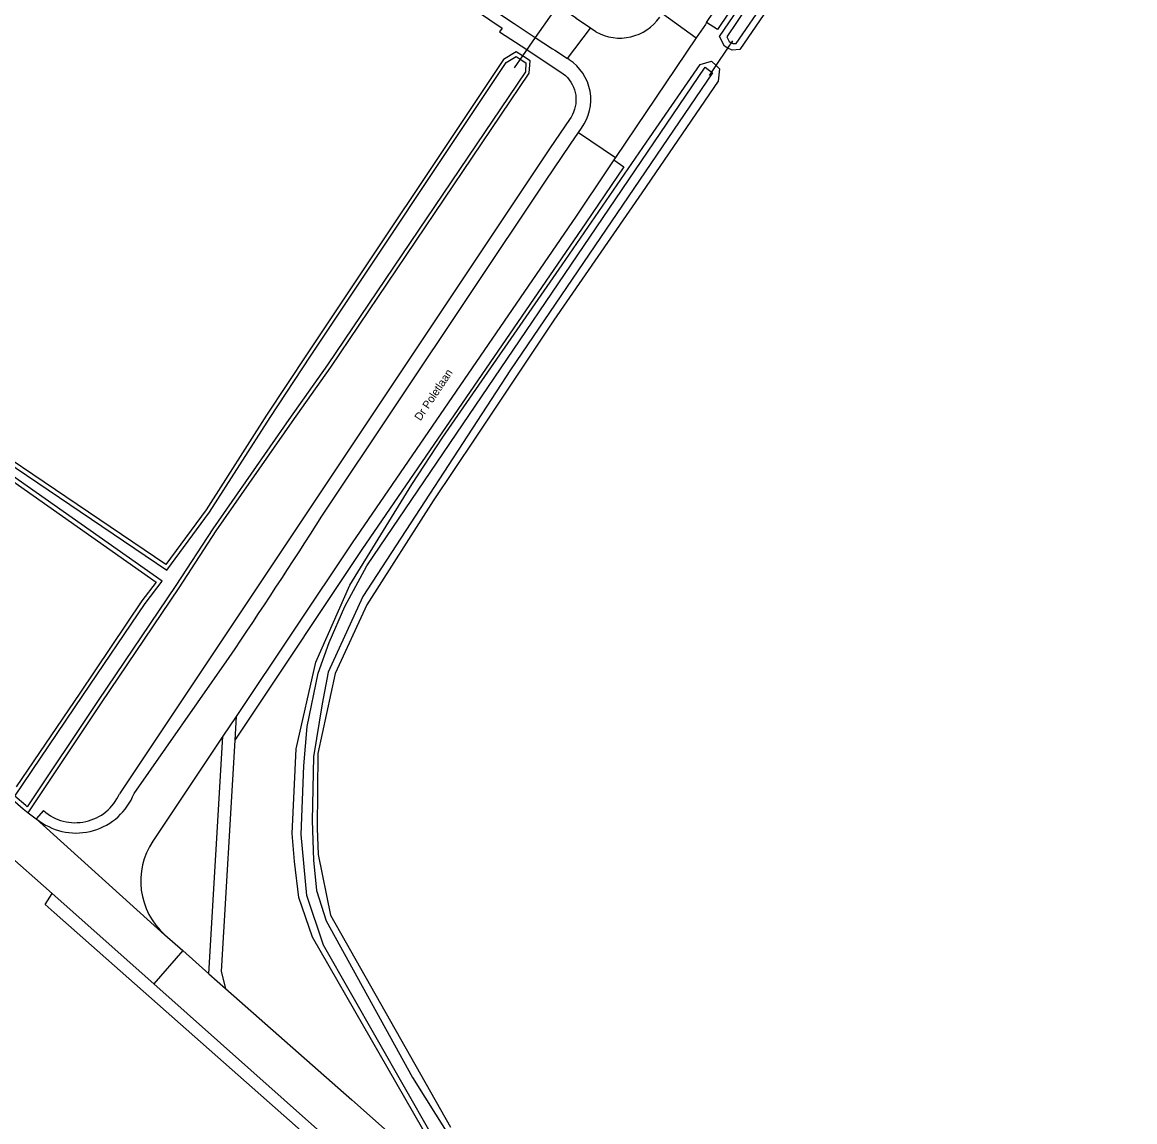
# Model space of a CAD drawing. Extents: x 158132 to 159658, y 385257 to 387209.
# Drawn here: x 159295.8 to 159434.8, y 385860.1 to 385997.6 of the extents above; entities that cross this region are included whole.
import ezdxf

# ---------------------------------------------------------------- set-up
doc = ezdxf.new("R2010")
doc.units = 0
for name, color, linetype in [('IMGEO_Berm_groen', 7, 'Continuous'), ('IMGEO_Duiker', 7, 'Continuous'), ('IMGEO_Fietspad_open', 7, 'Continuous'), ('IMGEO_Groenvoorziening', 7, 'Continuous'), ('IMGEO_Loofbos', 7, 'Continuous'), ('IMGEO_Openbare_ruimte_label', 7, 'Continuous'), ('IMGEO_Parkeervlak_halfverhard', 7, 'Continuous'), ('IMGEO_Rijbaan_lokaal_gesloten', 7, 'Continuous'), ('IMGEO_Rijbaan_lokaal_open', 7, 'Continuous'), ('IMGEO_Voetpad_open', 7, 'Continuous'), ('IMGEO_Waterloop', 7, 'Continuous')]:
    doc.layers.add(name, color=color, linetype=linetype)

msp = doc.modelspace()

# ---------------------------------------------------------------- linework, layer by layer
at = {"layer": 'IMGEO_Berm_groen'}
msp.add_lwpolyline([(159369.74, 385980.34), (159370.97, 385979.48), (159366.24, 385972.46), (159338.24, 385931.62), (159323.76, 385909.93), (159322.34, 385907.8)], dxfattribs=at)
at = {"layer": 'IMGEO_Duiker'}
for points in [[(159364.38, 386002.06), (159363.53, 386000.84), (159362.95, 386000), (159362.67, 385999.6), (159359.91, 385995.65), (159358.31, 385993.36), (159357.26, 385991.85)], [(159381.7, 385990.88), (159382.52, 385992.13), (159383.99, 385994.33), (159384.59, 385995.24)]]:
    msp.add_lwpolyline(points, dxfattribs=at)
at = {"layer": 'IMGEO_Fietspad_open'}
msp.add_lwpolyline([(159434.84, 385765.65), (159432.59, 385767.85), (159428.81, 385771), (159421.75, 385777.33), (159373.58, 385820.69), (159370.76, 385823.15), (159357.19, 385835.22), (159344.98, 385846.27), (159299.79, 385886.27), (159298.65, 385887.27), (159299.53, 385888.62)], dxfattribs=at)
at = {"layer": 'IMGEO_Groenvoorziening'}
for points in [[(159296.52, 385898.73), (159305.68, 385912.46), (159315.38, 385926.85), (159320.01, 385933.95), (159329.51, 385947.59), (159334.35, 385954.45), (159359.16, 385991.19), (159359.26, 385992.74), (159358.31, 385993.36), (159357.52, 385993.86), (159355.92, 385992.89), (159331.4, 385956.1), (159326.33, 385948.43), (159318.77, 385936.58), (159313.74, 385929.75), (159277.73, 385954.11), (159246.09, 385976.87)], [(159244.88, 385975.29), (159277.36, 385952.3), (159312.54, 385927.56), (159310.72, 385925.2), (159302.96, 385913.66), (159295.04, 385901.96)]]:
    msp.add_lwpolyline(points, dxfattribs=at)
at = {"layer": 'IMGEO_Loofbos'}
for points in [[(159395.39, 386008.63), (159389.48, 386000), (159385.48, 385994.17), (159384.51, 385994.05), (159383.99, 385994.33), (159383.56, 385994.57), (159382.93, 385995.79), (159385.79, 386000), (159393.1, 386010.75), (159408.76, 386034.08), (159422.33, 386053.78), (159431.59, 386068.19), (159433.03, 386069.16), (159433.99, 386068.57), (159434, 386066.48), (159423.66, 386050.6), (159412.31, 386033.82), (159395.39, 386008.63)], [(159346.82, 385857.51), (159332.05, 385883.18), (159330.37, 385888.12), (159329.82, 385892.62), (159329.54, 385896.14), (159330.03, 385906.73), (159332.47, 385917.55), (159336.73, 385927.18), (159344.46, 385939.76), (159348.34, 385945.7), (159363.26, 385967.23), (159373.82, 385982.57), (159380.53, 385992.28), (159381.94, 385992.69), (159382.52, 385992.13), (159382.93, 385991.72), (159382.77, 385990.18), (159373.21, 385976.23), (159362.22, 385960.32), (159352.38, 385945.57), (159347.15, 385937.71), (159338.84, 385924.72), (159334.9, 385916.12), (159332.73, 385906.12), (159332.66, 385896.81), (159332.78, 385893.49), (159334.32, 385885.93), (159349.29, 385859.41)]]:
    msp.add_lwpolyline(points, dxfattribs=at)
at = {"layer": 'IMGEO_Parkeervlak_halfverhard'}
msp.add_lwpolyline([(159422.73, 386058.55), (159423.83, 386057.81), (159382.67, 385996.63), (159381.32, 385997.52)], dxfattribs=at)
at = {"layer": 'IMGEO_Rijbaan_lokaal_gesloten'}
for points in [[(159381.32, 385997.52), (159382.99, 386000), (159404.94, 386032.53), (159421.5, 386056.95)], [(159366.81, 385996.83), (159365.02, 385998.03), (159365, 385998.05), (159362.67, 385999.6), (159362.07, 386000), (159354.98, 386004.72), (159349.29, 386008.47), (159338.61, 386015.61), (159336.36, 386017.41)], [(159348.48, 386003.28), (159353.37, 386000), (159357.27, 385997.38), (159359.91, 385995.65), (159362.06, 385994.25), (159362.35, 385994.06), (159363.93, 385993.02)], [(159381.32, 385997.52), (159381.21, 385997.35), (159381.17, 385997.29), (159380.03, 385995.6)], [(159333.23, 385935.8), (159361.2, 385977.7), (159364.33, 385982.31), (159365.31, 385983.76)], [(159369.94, 385980.63), (159369.74, 385980.34)], [(159369.74, 385980.34), (159368.91, 385979.1), (159365, 385973.3), (159337, 385932.46), (159322.51, 385910.76)], [(159309.76, 385901.11), (159321.64, 385918.13)], [(159322.51, 385910.76), (159320.85, 385908.28)], [(159320.85, 385908.28), (159312.11, 385895.18)], [(159294.52, 385900.43), (159295.89, 385899.22), (159296.52, 385898.73)], [(159296.52, 385898.73), (159297.54, 385897.96)], [(159297.54, 385897.96), (159297.93, 385897.67)], [(159297.54, 385897.96), (159313.57, 385883.46), (159313.62, 385883.46)], [(159299.53, 385888.62), (159293.41, 385894.06)], [(159312.23, 385877.33), (159299.53, 385888.62)], [(159313.62, 385883.46), (159315.86, 385881.48)], [(159315.86, 385881.48), (159312.23, 385877.33)], [(159315.86, 385881.48), (159319.11, 385878.6)], [(159319.11, 385878.6), (159321.2, 385876.76)], [(159414.24, 385786.36), (159414.14, 385786.45), (159374.77, 385821.88), (159371.86, 385824.45), (159358.33, 385836.48), (159332.7, 385859.13), (159312.23, 385877.33)], [(159321.2, 385876.76), (159336.97, 385862.82), (159375.8, 385828.33), (159378.77, 385825.67), (159417.87, 385790.77), (159418.01, 385790.94), (159418.04, 385790.91)]]:
    msp.add_lwpolyline(points, dxfattribs=at)
for centre, radius, start, end in [((158703.05, 386336.47), 746.77, 325.93016, 327.55151), ((159302.51, 385903.98), 7.79, 234.0313, 338.4243), ((159319.59, 385890.18), 9, 146.2279, 228.3888)]:
    msp.add_arc(centre, radius, start, end, dxfattribs=at)
at = {"layer": 'IMGEO_Rijbaan_lokaal_open'}
for points in [[(159375.8, 385998.65), (159380.03, 385995.6)], [(159363.93, 385993.02), (159366.81, 385996.83)], [(159367.48, 385996.37), (159366.81, 385996.83)], [(159380.03, 385995.6), (159369.94, 385980.63)], [(159364.14, 385992.88), (159363.93, 385993.02)], [(159365.31, 385983.76), (159365.7, 385984.33)], [(159365.31, 385983.76), (159369.94, 385980.63)]]:
    msp.add_lwpolyline(points, dxfattribs=at)
for centre, radius, start, end in [((159370.47, 386001.66), 6.08, 240.5287, 325.3494), ((159360.87, 385987.87), 5.98, 323.7316, 56.858)]:
    msp.add_arc(centre, radius, start, end, dxfattribs=at)
at = {"layer": 'IMGEO_Voetpad_open'}
for points in [[(159347.79, 386002.25), (159355.76, 385996.83), (159355.45, 385996.37), (159358.85, 385994.13), (159359.75, 385993.54), (159363.12, 385991.32), (159363.41, 385991.12), (159363.68, 385990.89), (159363.93, 385990.64), (159364.15, 385990.36), (159364.36, 385990.07), (159364.53, 385989.76), (159364.68, 385989.44), (159364.8, 385989.11), (159364.89, 385988.77), (159364.96, 385988.42), (159364.99, 385988.07), (159364.99, 385987.71), (159364.96, 385987.36), (159364.9, 385987.01), (159364.81, 385986.67), (159364.7, 385986.33), (159364.55, 385986.01), (159364.38, 385985.7), (159364.18, 385985.41), (159361.76, 385981.84), (159307.93, 385901.08)], [(159322.51, 385910.76), (159322.34, 385907.8)], [(159319.11, 385878.6), (159320.85, 385908.28)], [(159322.34, 385907.8), (159320.63, 385878.88), (159321.2, 385876.76)], [(159298.44, 385898.99), (159297.54, 385897.96)]]:
    msp.add_lwpolyline(points, dxfattribs=at)
msp.add_arc((159302.42, 385903.49), 6.01, 228.5204, 336.4067, dxfattribs=at)
at = {"layer": 'IMGEO_Waterloop'}
for points in [[(159384.37, 385995.04), (159384.43, 385995.01), (159384.66, 385994.88), (159385.02, 385994.92), (159388.81, 386000.45), (159394.73, 386009.08), (159411.64, 386034.26), (159422.99, 386051.04), (159433.2, 386066.71), (159433.19, 386068.12), (159433.05, 386068.2), (159432.17, 386067.61), (159423, 386053.34), (159409.42, 386033.63), (159393.76, 386010.3), (159386.45, 385999.55), (159383.86, 385995.74), (159384.16, 385995.15), (159384.37, 385995.04)], [(159277.45, 385953.7), (159313.86, 385929.06), (159319.19, 385936.3), (159326.76, 385948.15), (159331.82, 385955.82), (159356.28, 385992.52), (159357.51, 385993.27), (159358.02, 385992.94), (159358.74, 385992.48), (159358.67, 385991.36), (159333.93, 385954.74)], [(159346.93, 385858.51), (159333.43, 385882.16), (159331.36, 385888.39), (159330.63, 385896), (159330.97, 385904.58), (159331.39, 385909.5), (159332.79, 385916.17), (159334.15, 385919.99), (159336.11, 385924.49), (159338.86, 385929.59), (159381.14, 385991.94)], [(159381.14, 385991.94), (159382.08, 385991.22), (159356.82, 385954.11), (159338.34, 385925.74), (159334.01, 385916.28), (159333.25, 385912.33), (159332.19, 385905.7), (159332.02, 385897.76), (159332.19, 385892.79), (159332.57, 385889.01), (159333.76, 385885.19), (159344.54, 385865.62), (159348.96, 385858.57)], [(159333.93, 385954.74), (159329.1, 385947.88), (159319.6, 385934.23), (159314.96, 385927.13), (159305.26, 385912.74), (159296.4, 385899.46), (159296.21, 385899.61), (159294.87, 385900.8), (159303.37, 385913.38), (159311.13, 385924.9), (159313.26, 385927.67), (159277.66, 385952.71)]]:
    msp.add_lwpolyline(points, dxfattribs=at)

# ---------------------------------------------------------------- texts
at = {"layer": 'IMGEO_Openbare_ruimte_label'}
msp.add_text('Dr Poletlaan', height=1, rotation=56.294, dxfattribs=at).set_placement((159345.56, 385947.65))

doc.saveas('drawing.dxf')
